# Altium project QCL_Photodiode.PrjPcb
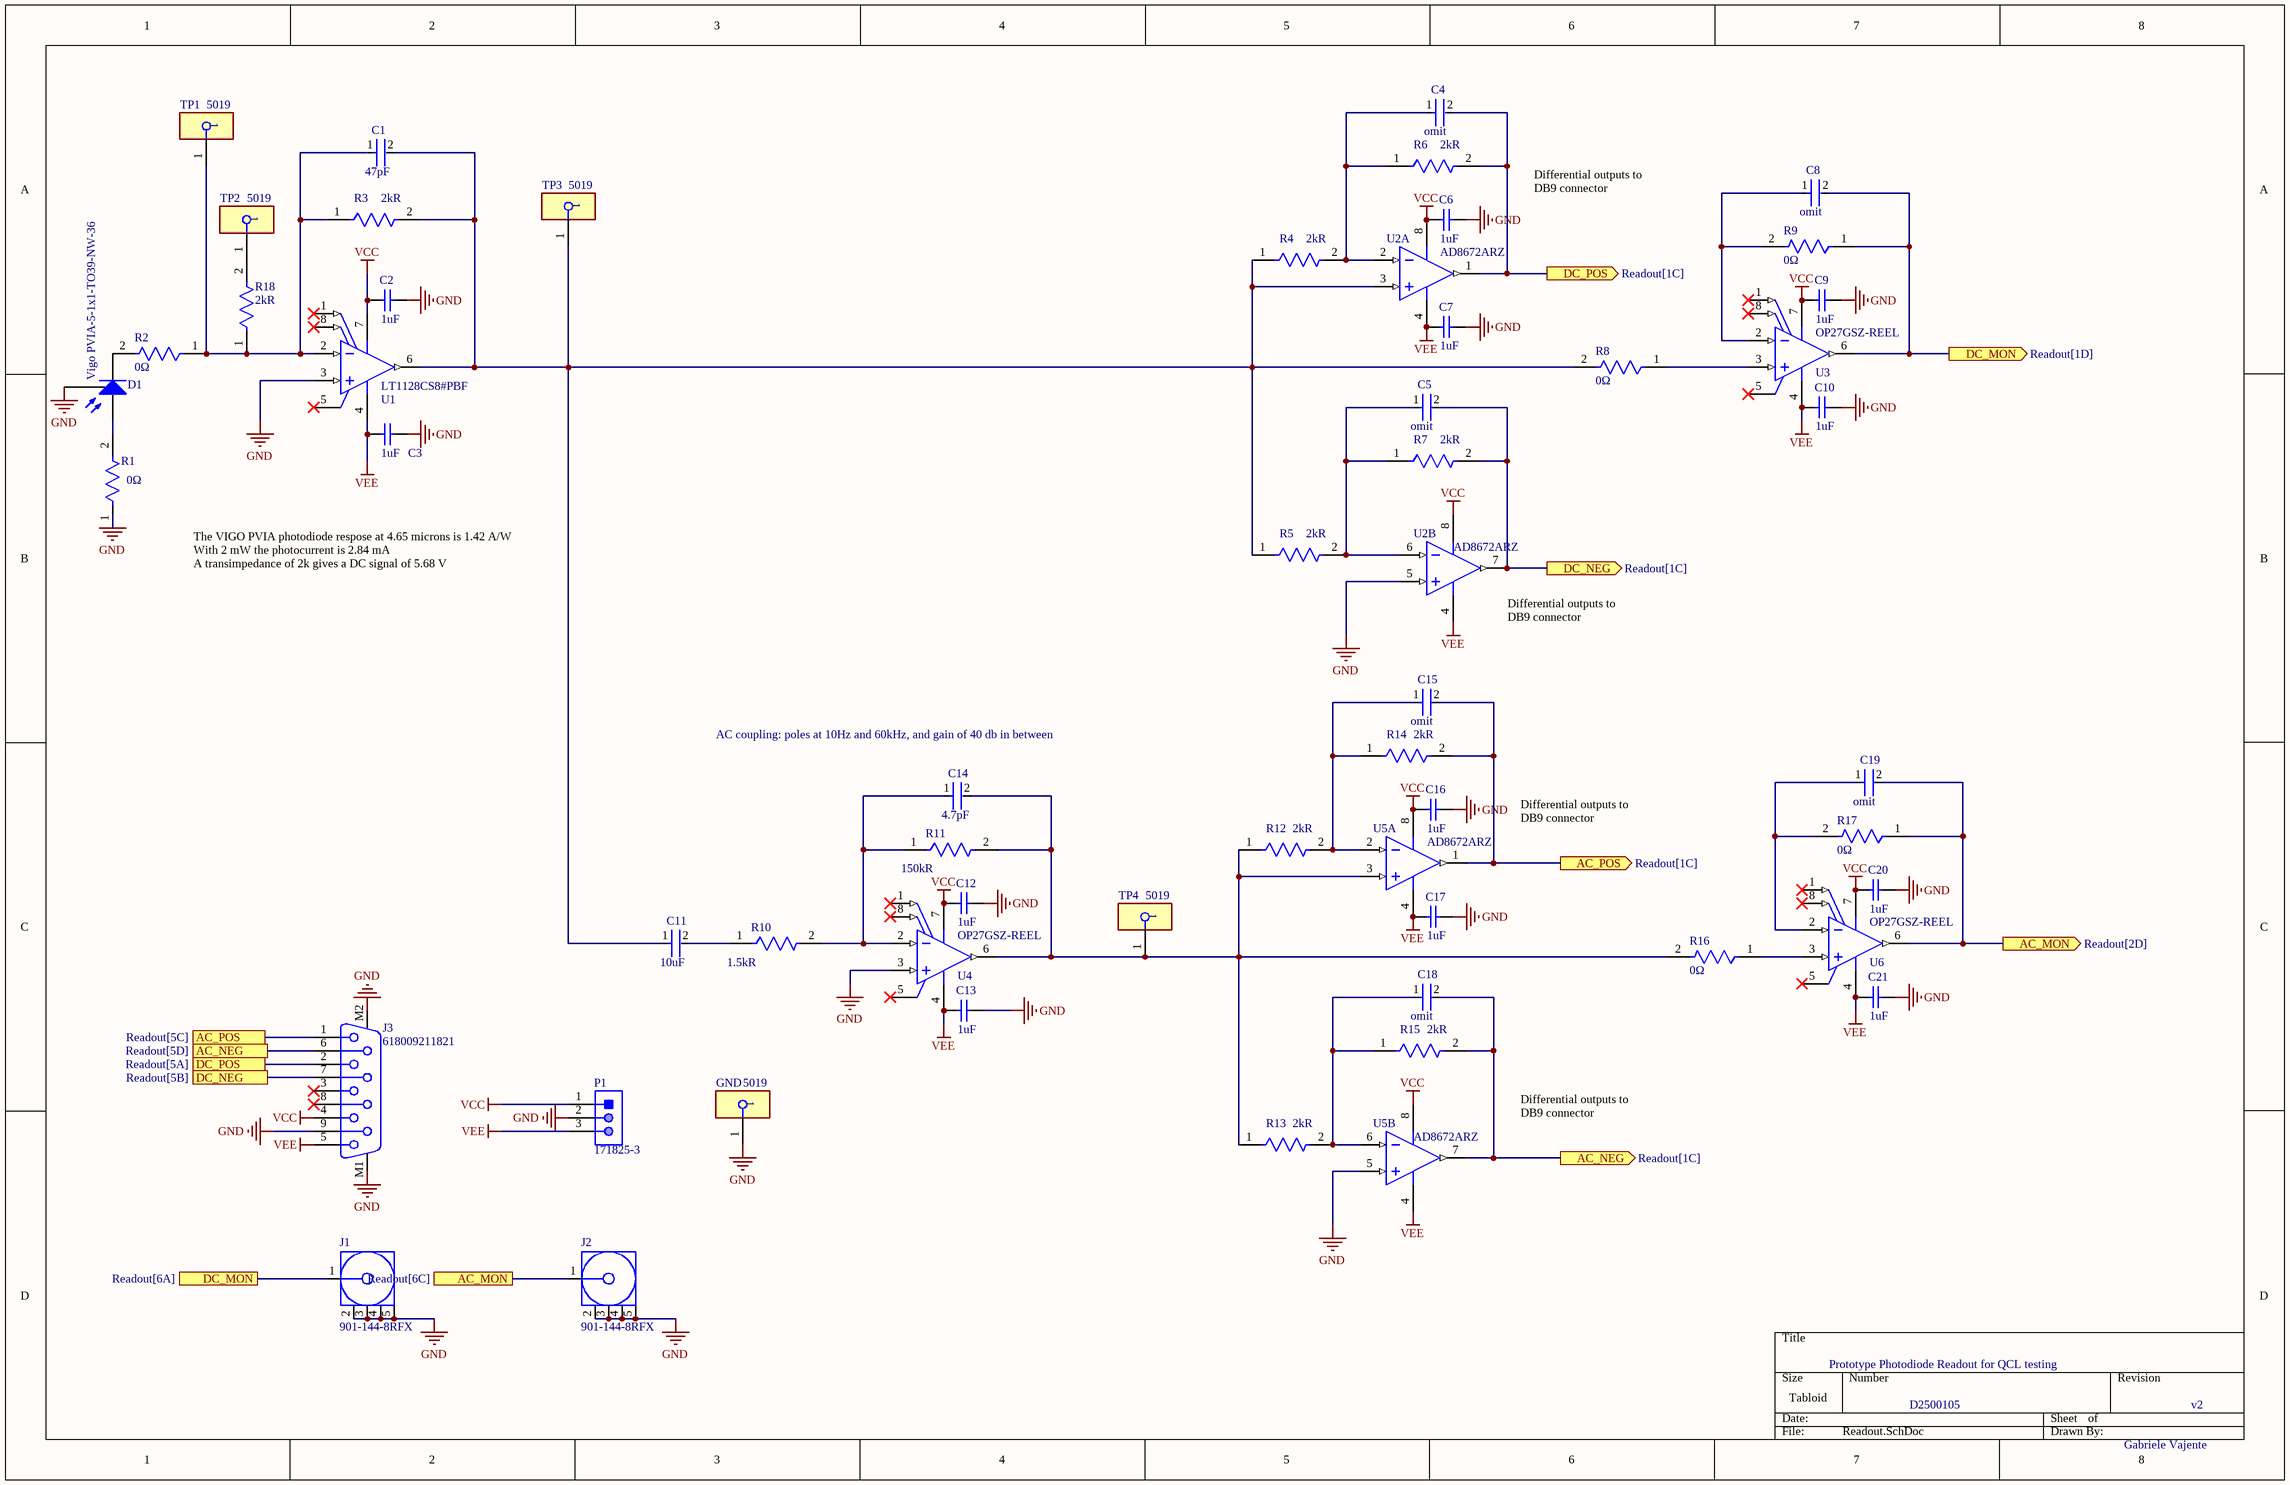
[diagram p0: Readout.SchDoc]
1 sheet, 55 parts. Net scope: flat (ports and power ports of the same name join across sheets).
Board file: Readout.PcbDoc

## Sheet Readout.SchDoc
size Tabloid; SheetNumber: 1; SheetTotal: 1

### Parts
C1  Capacitance: 47pF  [FP-1206-L_3_2_0_2-W_1_6_0-IPC_A]  (hidden comment: 12061A470JAT2A)
C2  Capacitance: 1uF  [CAPC3216X110X50LL20T25]  (hidden comment: C1206C105K5RACTU)
C3  Capacitance: 1uF  [CAPC3216X110X50LL20T25]  (hidden comment: C1206C105K5RACTU)
C4  Capacitance: omit  [FP-1206-L_3_2_0_2-W_1_6_0-IPC_A]  (hidden comment: 12061A470JAT2A)
C5  Capacitance: omit  [FP-1206-L_3_2_0_2-W_1_6_0-IPC_A]  (hidden comment: 12061A470JAT2A)
C6  Capacitance: 1uF  [CAPC3216X110X50LL20T25]  (hidden comment: C1206C105K5RACTU)
C7  Capacitance: 1uF  [CAPC3216X110X50LL20T25]  (hidden comment: C1206C105K5RACTU)
C8  Capacitance: omit  [FP-1206-L_3_2_0_2-W_1_6_0-IPC_A]  (hidden comment: 12061A470JAT2A)
C9  Capacitance: 1uF  [CAPC3216X110X50LL20T25]  (hidden comment: C1206C105K5RACTU)
C10  Capacitance: 1uF  [CAPC3216X110X50LL20T25]  (hidden comment: C1206C105K5RACTU)
C11  value 10uF  [FP-CL31-IPC_C]  (hidden comment: CL31A106KBHNNNE)
C12  Capacitance: 1uF  [CAPC3216X110X50LL20T25]  (hidden comment: C1206C105K5RACTU)
C13  Capacitance: 1uF  [CAPC3216X110X50LL20T25]  (hidden comment: C1206C105K5RACTU)
C14  Capacitance: 4.7pF  [FP-1206-L_3_2_0_2-W_1_6_0-IPC_A]  (hidden comment: 12065A4R7DAT2A)
C15  Capacitance: omit  [FP-1206-L_3_2_0_2-W_1_6_0-IPC_A]  (hidden comment: 12061A470JAT2A)
C16  Capacitance: 1uF  [CAPC3216X110X50LL20T25]  (hidden comment: C1206C105K5RACTU)
C17  Capacitance: 1uF  [CAPC3216X110X50LL20T25]  (hidden comment: C1206C105K5RACTU)
C18  Capacitance: omit  [FP-1206-L_3_2_0_2-W_1_6_0-IPC_A]  (hidden comment: 12061A470JAT2A)
C19  Capacitance: omit  [FP-1206-L_3_2_0_2-W_1_6_0-IPC_A]  (hidden comment: 12061A470JAT2A)
C20  Capacitance: 1uF  [CAPC3216X110X50LL20T25]  (hidden comment: C1206C105K5RACTU)
C21  Capacitance: 1uF  [CAPC3216X110X50LL20T25]  (hidden comment: C1206C105K5RACTU)
D1  Vigo PVIA-5-1x1-TO39-NW-36  [TO-39]
GND  5019  [FP-5019-MFG]
J1  901-144-8RFX  [AMPH-901-144-8RFX_V]
J2  901-144-8RFX  [AMPH-901-144-8RFX_V]
J3  618009211821  [618009211821]
P1  171825-3  [TECO-171825-3_V]
R1  value 0Ω  [FP-RC1206-MFG]  (hidden comment: RC1206JR-070RL)
R2  value 0Ω  [FP-RC1206-MFG]  (hidden comment: RC1206JR-070RL)
R3  Resistance: 2kR  [FP-CRCW1206-e3-IPC_A]  (hidden comment: CRCW12062K00FKEA)
R4  Resistance: 2kR  [FP-CRCW1206-e3-IPC_A]  (hidden comment: CRCW12062K00FKEA)
R5  Resistance: 2kR  [FP-CRCW1206-e3-IPC_A]  (hidden comment: CRCW12062K00FKEA)
R6  Resistance: 2kR  [FP-CRCW1206-e3-IPC_A]  (hidden comment: CRCW12062K00FKEA)
R7  Resistance: 2kR  [FP-CRCW1206-e3-IPC_A]  (hidden comment: CRCW12062K00FKEA)
R8  value 0Ω  [FP-RC1206-MFG]  (hidden comment: RC1206JR-070RL)
R9  value 0Ω  [FP-RC1206-MFG]  (hidden comment: RC1206JR-070RL)
R10  Resistance: 1.5kR  [FP-CRCW1206-e3-IPC_C]  (hidden comment: CRCW12061K50FKEA)
R11  Resistance: 150kR  [FP-CRCW1206-e3-IPC_B]  (hidden comment: CRCW1206150KFKEA)
R12  Resistance: 2kR  [FP-CRCW1206-e3-IPC_A]  (hidden comment: CRCW12062K00FKEA)
R13  Resistance: 2kR  [FP-CRCW1206-e3-IPC_A]  (hidden comment: CRCW12062K00FKEA)
R14  Resistance: 2kR  [FP-CRCW1206-e3-IPC_A]  (hidden comment: CRCW12062K00FKEA)
R15  Resistance: 2kR  [FP-CRCW1206-e3-IPC_A]  (hidden comment: CRCW12062K00FKEA)
R16  value 0Ω  [FP-RC1206-MFG]  (hidden comment: RC1206JR-070RL)
R17  value 0Ω  [FP-RC1206-MFG]  (hidden comment: RC1206JR-070RL)
R18  Resistance: 2kR  [FP-CRCW1206-e3-IPC_A]  (hidden comment: CRCW12062K00FKEA)
TP1  5019  [FP-5019-MFG]
TP2  5019  [FP-5019-MFG]
TP3  5019  [FP-5019-MFG]
TP4  5019  [FP-5019-MFG]
U1  LT1128CS8#PBF  [LT-S8-8_M]
U2  AD8672ARZ  [ADI-R-8_N]  (parts A,B of 2)
U3  OP27GSZ-REEL  [ADI-R-8_M]
U4  OP27GSZ-REEL  [ADI-R-8_M]
U5  AD8672ARZ  [ADI-R-8_N]  (parts A,B of 2)
U6  OP27GSZ-REEL  [ADI-R-8_M]

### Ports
AC_MON (out, see Readout[2D]), AC_MON (see Readout[6C]), AC_NEG (out, see Readout[1C]), AC_NEG (see Readout[5D]), AC_POS (out, see Readout[1C]), AC_POS (see Readout[5C]), DC_MON (out, see Readout[1D]), DC_MON (see Readout[6A]), DC_NEG (out, see Readout[1C]), DC_NEG (see Readout[5B]), DC_POS (out, see Readout[1C]), DC_POS (see Readout[5A])

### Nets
GND: C2.2 C3.2 C6.2 C7.2 C9.2 C10.2 C12.2 C13.2 C16.2 C17.2 C20.2 C21.2 D1.3(in) GND.1 J1.2 J1.3 J1.4 J1.5 J2.2 J2.3 J2.4 J2.5 J3.9 J3.M1 J3.M2 P1.2 R1.1 U1.3(+IN) U2.5(+IN_B) U4.3(+IN) U5.5(+IN_B)
VCC: C2.1 C6.1 C9.1 C12.1 C16.1 C20.1 J3.4 P1.1 U1.7(V+) U2.8(+V) U3.7(V+) U4.7(V+) U5.8(+V) U6.7(V+)
VEE: C3.1 C7.1 C10.1 C13.1 C17.1 C21.1 J3.5 P1.3 U1.4(V-) U2.4(-V) U3.4(V-) U4.4(V-) U5.4(-V) U6.4(V-)
NetC1_1: C1.1 R2.1 R3.1 R18.1 TP1.1 U1.2(-IN)
NetC1_2: C1.2 C11.1 R3.2 R4.1 R5.1 R8.2 TP3.1 U1.6(OUT) U2.3(+IN_A)
NetC4_1: C4.1 R4.2 R6.1 U2.2(-IN_A)
NetC4_2: C4.2 J3.2 R6.2 U2.1(OUT_A) ; port DC_POS
NetC5_1: C5.1 R5.2 R7.1 U2.6(-IN_B)
NetC5_2: C5.2 J3.7 R7.2 U2.7(OUT_B) ; port DC_NEG
NetC8_1: C8.1 R9.2 U3.2(-IN)
NetC8_2: C8.2 J1.1 R9.1 U3.6(OUT) ; port DC_MON
NetC11_2: C11.2 R10.1
NetC14_1: C14.1 R10.2 R11.1 U4.2(-IN)
NetC14_2: C14.2 R11.2 R12.1 R13.1 R16.2 TP4.1 U4.6(OUT) U5.3(+IN_A)
NetC15_1: C15.1 R12.2 R14.1 U5.2(-IN_A)
NetC15_2: C15.2 J3.1 R14.2 U5.1(OUT_A) ; port AC_POS
NetC18_1: C18.1 R13.2 R15.1 U5.6(-IN_B)
NetC18_2: C18.2 J3.6 R15.2 U5.7(OUT_B) ; port AC_NEG
NetC19_1: C19.1 R17.2 U6.2(-IN)
NetC19_2: C19.2 J2.1 R17.1 U6.6(OUT) ; port AC_MON
NetD1_1: D1.1(A) R1.2
NetD1_2: D1.2(K) R2.2
NetR8_1: R8.1 U3.3(+IN)
NetR16_1: R16.1 U6.3(+IN)
NetR18_2: R18.2 TP2.1

Not connected (* = marked no-connect by the designer): J3 3* 8*; U1 1(VOS_TRIM)* 5(OVERCOMP)* 8(VOS_TRIM)*; U3 1(VOS_TRIM)* 5(NC)* 8(VOS_TRIM)*; U4 1(VOS_TRIM)* 5(NC)* 8(VOS_TRIM)*; U6 1(VOS_TRIM)* 5(NC)* 8(VOS_TRIM)*

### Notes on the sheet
- Differential outputs to DB9 connector
- The VIGO PVIA photodiode respose at 4.65 microns is 1.42 A/W
  With 2 mW the photocurrent is 2.84 mA
  A transimpedance of 2k gives a DC signal of 5.68 V
- (near U2) Differential outputs to DB9 connector
- AC coupling: poles at 10Hz and 60kHz, and gain of 40 db in between
- Prototype Photodiode Readout for QCL testing
- D2500105
- v2
- Gabriele Vajente

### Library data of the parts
C1 C4 C5 C8 C14 C15 C18 C19 = CMP-04427-018828-1: General Purpose Ceramic Capacitor, 1206, 47pF, 5%, NP0, 30ppm/°C, 100V; Dielectric: C0G; Insulation Resistance: 100GR; Dissipation Factor: 2.5%
C2 C3 C6 C7 C9 C10 C12 C13 C16 C17 C20 C21 = CMP-2000-06011-1: Chip Capacitor, 1 uF, +/- 10%, 50 V, -55 to 125 degC, 1206 (3216 Metric), RoHS, Tape and Reel; Manufacturer: Kemet; Case Height: 1mm; Dielectric: X7R; Voltage Rating: 50V; Temperature Coefficient / Code: +/-15%; Case Length: 3.2mm; Case Width: 1.6mm; Type: SMDMLCCX7R6.3-250VDCCommericalGrade; Class: Class1; Capacitance - nF: 1000nF
C11 = CMP-13271-000014-1: CAP CER 3.3UF 25V X7R 1206; Manufacturer: Samsung; Manufacturer Part Number: CL31B335KAHVPNE; Temperature Coefficient: 15%; Material: Ceramic; Automotive Grade: Grade 1; Tolerance: 10%
D1 = Photodiode: RESP: 0.5; Rint: 10m; IS: 1N; N: 1.35; CJO: 60P; BV: 60; SimulationGenericComponent: True
GND TP1-TP4 = CMP-1672-00008-2: NexarPartId: 22052288; Number of Contacts: 1
J1 J2 = CMP-2000-05706-1: Coaxial Connector, 18 GHz, 50 Ohm, -65 to 165 degC, 5-Pin THD, RoHS, Bulk; Manufacturer: Amphenol; Contact Termination: Solder; Dielectric Material: Polytetrafluoroethylene(PTFE); Frequency - Max: 18GHz; Body Material: Brass; Other Names: 901-144-8-RFX9011448RFXARFX1231; Center Contact Plating: Gold; Connector Type: Jack,FemaleSocket; Center Contact Material: BerylliumCopper; Impedance: 50Ohm; 3D Model: 901-144-8RFX.igs; Online Catalog: SMA,RFX; Connector Style: SMA
J3 = CMP-1502-00208-2: NexarPartId: 89205517; Insulation Resistance: 5GΩ; Current Rating: 3A; Contact Resistance: 30mΩ; Gender: Female; Operating Supply Voltage: 125V; Pitch: 2.77mm
P1 = CMP-2000-07494-1: Male Header, Pitch 2.5 mm, 1 x 3 Position, Height 10.4 mm, Tail Length 3.6 mm, / -20 to 95 degC / , RoHS, Bulk; Manufacturer: TE Connectivity; Mating Alignment: Yes(With); Tail Length: 0.142inch; Mating Post Length: 7.5mm; PCB Thickness: 0.063inch; PCB Mount Alignment: No(Without); Voltage Rating: 350V; Max Voltage Rating (AC): 250V; Plating Thickness: 0.8um; PCB Mounting Orientation: Vertical; Number of Positions: 3; PCB Mount Retention: Without; Max Current Rating: 3.5A; Max Voltage Rating (DC): 350.25kV; Pitch: 2.5mm; Approvals: UL; Contact Resistance: 20mOhm
R1 R2 R8 R9 R16 R17 = CMP-2100-03681-2: RES SMD 0 OHM JUMPER 1/4W 1206; Manufacturer: YAGEO; Voltage Rating: 200V; Temperature Coefficient: 300ppm/°C; Power Rating: 0.25W; Tolerance: 5%
R3-R7 R12-R15 R18 = CMP-1014-00542-3: RES Thick Film, 2kΩ, 1%, 0.25W, 100ppm/°C, 1206; Max Power Dissipation: 250mW; Voltage Rating: 200V
R10 = CMP-02407-002229-1: RES Thick Film, 1.5kΩ, 1%, 0.25W, 100ppm/°C, 1206; Voltage Rating (DC): 200V; Power Rating: 250mW
R11 = CMP-2003-01810-2: RES Thick Film, 150kΩ, 1%, 0.25W, 100ppm/°C, 1206; Max Power Dissipation: 250mW; Voltage Rating: 200V
U1 = CMP-0359-03002-2: Single Channel, Low Noise High Speed Operational Amplifier, 20 MHz Typical GBW, 6 V/us Typical SR, 8 to 44 V, 8-Pin SOIC (S8-8), Commercial, Pb-Free; Linear Technology Part Number: LT1128; Manufacturer: Linear Technology; Vos (mV) Typical: 0.01; Is (mA) Typical: 7.4; GBW (MHz) Typical: 20; Vs Min (V): 8; Channels (#): 1; SR (V/us) Typical: 6; Vs Max (V): 44
U2 U5 = CMP-0384-00608-2: Double Channel Wide Bandwidth Operational Amplifier, 10 MHz BW, 4 V/us SR, Industrial, 8-pin SOIC (R-8), Tube; Manufacturer: Analog Devices; Generic Part Number: AD8672; V Span Max: 30V; Small Signal Bandwidth: 10MHz; V Span Min: 10V; Input Offset Voltage: 20uV; Amplifiers Per Package: 2; Iq/Amp: 3.5mA; Input Bias Current: 3nA; Slew Rate: 4V/us
U3 U4 U6 = CMP-0384-01390-1: Single Channel Low Noise Operational Amplifier, 8 MHz BW, 2.8 V/us SR, Industrial, 8-pin SOIC (R-8), Reel; Manufacturer: Analog Devices; Generic Part Number: OP27; Input Offset Voltage: 30uV; Iq/Amp: 5.7mA; V Span Max: 44V; V Span Min: 8V; Small Signal Bandwidth: 8MHz; Amplifiers Per Package: 1; Input Bias Current: 15nA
